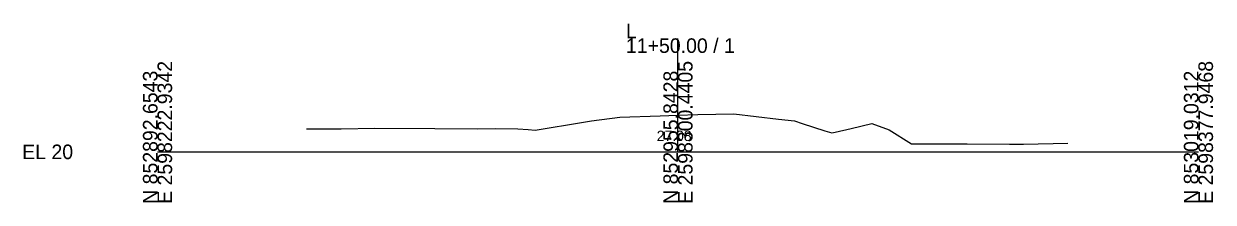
# Model space of a CAD drawing. Extents: x -26 to 1203, y -10 to 9526.
# Drawn here: x -25.7 to 202.8, y 1490.3 to 1524.6 of the extents above; entities that cross this region are included whole.
import ezdxf

# ---------------------------------------------------------------- set-up
doc = ezdxf.new("R2010")
doc.units = 0
for name, color, linetype in [('Exist Cross Section Cell', 7, 'Continuous'), ('Exist XS Center Line Elevation Label', 7, 'Continuous'), ('Exist XS Ground Line', 7, 'Continuous')]:
    doc.layers.add(name, color=color, linetype=linetype)

msp = doc.modelspace()

# ---------------------------------------------------------------- linework, layer by layer
at = {"layer": 'Exist Cross Section Cell'}
for p, q in [((100, 1500), (100, 1521.83)), ((0, 1500), (100, 1500)), ((100, 1500), (200, 1500))]:
    msp.add_line(p, q, dxfattribs=at)
at = {"layer": 'Exist XS Ground Line'}
for p, q in [((83.37, 1505.94), (88.81, 1506.66)), ((88.81, 1506.66), (96.58, 1506.94)), ((96.58, 1506.94), (99.93, 1507.08)), ((99.93, 1507.08), (103.82, 1507.16)), ((103.82, 1507.16), (110.71, 1507.28)), ((110.71, 1507.28), (119.32, 1506.28)), ((119.32, 1506.28), (122.37, 1505.95)), ((28.62, 1504.45), (35.29, 1504.45)), ((35.29, 1504.45), (41.73, 1504.57)), ((41.73, 1504.57), (53.31, 1504.48)), ((53.31, 1504.48), (61.47, 1504.4)), ((61.47, 1504.4), (65.01, 1504.46)), ((65.01, 1504.46), (69.24, 1504.45)), ((69.24, 1504.45), (71.19, 1504.28)), ((71.19, 1504.28), (72.55, 1504.17)), ((72.55, 1504.17), (76.78, 1504.86)), ((76.78, 1504.86), (77.59, 1505)), ((77.59, 1505), (83.37, 1505.94)), ((122.37, 1505.95), (123.88, 1505.42)), ((123.88, 1505.42), (128.2, 1504.03)), ((128.2, 1504.03), (129.55, 1503.63)), ((129.55, 1503.63), (130.22, 1503.8)), ((130.22, 1503.8), (133.26, 1504.5)), ((133.26, 1504.5), (137.22, 1505.42)), ((137.22, 1505.42), (140.58, 1504.26)), ((140.58, 1504.26), (144.88, 1501.54)), ((144.88, 1501.54), (150.25, 1501.53)), ((150.25, 1501.53), (155.55, 1501.57)), ((155.55, 1501.57), (163.71, 1501.46)), ((163.71, 1501.46), (166.39, 1501.49)), ((166.39, 1501.49), (174.92, 1501.7))]:
    msp.add_line(p, q, dxfattribs=at)

# ---------------------------------------------------------------- texts
at = {"layer": 'Exist Cross Section Cell'}
for s, p in [('L', (90, 1521.83)), ('11+50.00 / 1', (90, 1519.03)), ('EL 20', (-26, 1498.6))]:
    msp.add_text(s, height=2.8, dxfattribs=at).set_placement(p)
for s, p in [('N 852892.6543', (0, 1490)), ('E 2598222.9342', (2.8, 1490)), ('N 852955.8428', (100, 1490)), ('E 2598300.4405', (102.8, 1490)), ('N 853019.0312', (200, 1490)), ('E 2598377.9468', (202.8, 1490))]:
    msp.add_text(s, height=2.8, rotation=90, dxfattribs=at).set_placement(p)
at = {"layer": 'Exist XS Center Line Elevation Label'}
msp.add_text('27.08', height=2, dxfattribs=at).set_placement((95.93, 1502.08))

doc.saveas('drawing.dxf')
